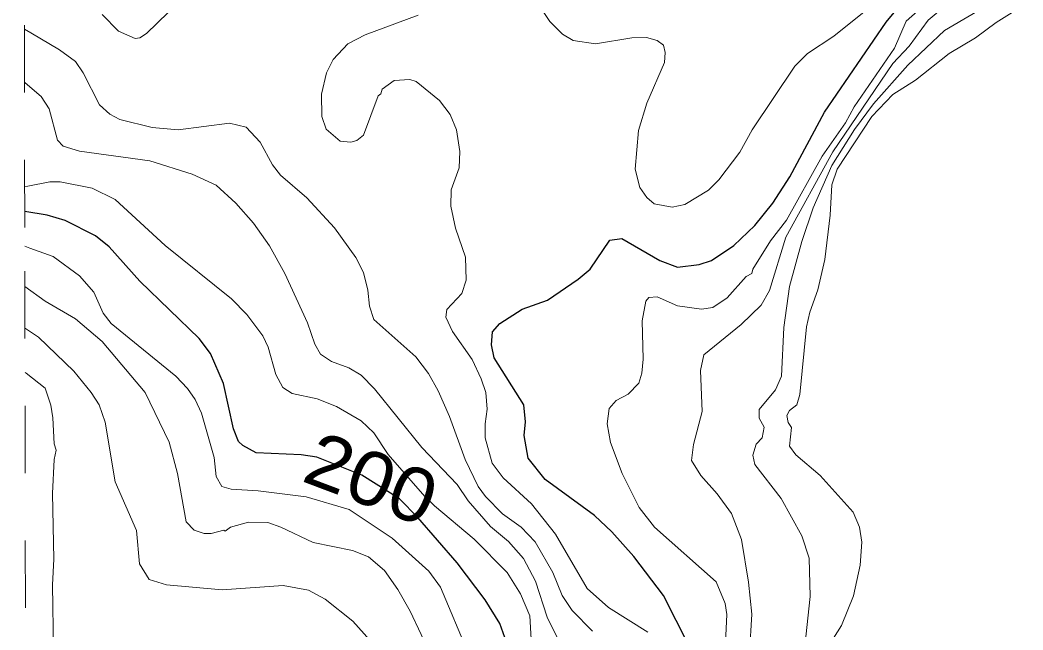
# Model space of a CAD drawing. Extents: x 474.5 to 500, y 7345.7 to 7373.4.
# Drawn here: x 474.546 to 476.034, y 7355.286 to 7356.191 of the extents above; entities that cross this region are included whole.
import ezdxf
from ezdxf.enums import TextEntityAlignment as Align

# ---------------------------------------------------------------- set-up
doc = ezdxf.new("R2010")
doc.units = 0
doc.header["$LTSCALE"] = 0.032
doc.linetypes.add('SHORT_DASHED', pattern=[2.7, 1.5, -1.2])
for name, color, linetype, lineweight in [('1', 7, 'Continuous', 25), ('2', 7, 'Continuous', 13), ('22', 7, 'SHORT_DASHED', 13)]:
    doc.layers.add(name, color=color, linetype=linetype, lineweight=lineweight)
doc.layers.add('61', color=7, linetype='Continuous')

msp = doc.modelspace()

# ---------------------------------------------------------------- linework, layer by layer
at = {"layer": '1'}
for points in [[(475.5384, 7355.2627), (475.5012, 7355.3372), (475.4569, 7355.3951), (475.4242, 7355.4317), (475.3987, 7355.4556), (475.3253, 7355.5092), (475.3002, 7355.5406), (475.2945, 7355.5744), (475.296, 7355.5946), (475.2937, 7355.6201), (475.2499, 7355.6898), (475.2458, 7355.7088), (475.2475, 7355.7283), (475.2583, 7355.7408), (475.2911, 7355.7621), (475.329, 7355.7755), (475.3744, 7355.8064), (475.3923, 7355.8214), (475.4213, 7355.8646), (475.4391, 7355.8669), (475.4957, 7355.834), (475.5219, 7355.8241), (475.554, 7355.8281), (475.5721, 7355.8342), (475.6052, 7355.8566), (475.6365, 7355.886), (475.6634, 7355.9191), (475.6887, 7355.9583), (475.7399, 7356.0545), (475.8315, 7356.1881), (475.8634, 7356.2264)], [(475.2705, 7355.2608), (475.258, 7355.2953), (475.2364, 7355.3308), (475.1947, 7355.3856), (475.1362, 7355.4526), (475.1091, 7355.4803), (475.0534, 7355.5158), (474.9864, 7355.5421), (474.9631, 7355.5457), (474.8964, 7355.5489), (474.8768, 7355.5595), (474.8701, 7355.5656), (474.8629, 7355.5844), (474.8478, 7355.6514), (474.8287, 7355.6961), (474.812, 7355.7185), (474.7238, 7355.8035), (474.6783, 7355.8545), (474.6581, 7355.8709), (474.6131, 7355.8937), (474.5861, 7355.9016), (474.5531, 7355.9068)]]:
    msp.add_lwpolyline(points, dxfattribs=at)
at = {"layer": '2'}
for points in [[(475.9113, 7356.2342), (475.861, 7356.1896), (475.844, 7356.1493), (475.7838, 7356.0622), (475.771, 7356.0383), (475.7367, 7355.9891), (475.6836, 7355.894), (475.6596, 7355.8632), (475.6334, 7355.8214), (475.6321, 7355.8149), (475.6238, 7355.8103), (475.5954, 7355.7787), (475.5741, 7355.7643), (475.5576, 7355.7619), (475.5217, 7355.7671), (475.4915, 7355.7801), (475.4794, 7355.7795), (475.475, 7355.7737), (475.4692, 7355.7448), (475.4708, 7355.6879), (475.469, 7355.6672), (475.4644, 7355.652), (475.4484, 7355.6358), (475.4308, 7355.6264), (475.4204, 7355.6147), (475.4174, 7355.5918), (475.4226, 7355.564), (475.4395, 7355.518), (475.4647, 7355.4677), (475.4879, 7355.4384), (475.5792, 7355.3573), (475.5927, 7355.3252), (475.5952, 7355.309), (475.593, 7355.2671)], [(475.6327, 7356.0282), (475.6143, 7355.9948), (475.583, 7355.9538), (475.5676, 7355.9385), (475.5327, 7355.9173), (475.5139, 7355.9136), (475.4872, 7355.9184), (475.4765, 7355.9275), (475.4659, 7355.9425), (475.4588, 7355.9699), (475.4641, 7356.0273), (475.4762, 7356.0679), (475.5026, 7356.128), (475.5034, 7356.1431), (475.5008, 7356.1536), (475.4914, 7356.1608), (475.4758, 7356.1654), (475.4542, 7356.1646), (475.4003, 7356.156), (475.367, 7356.1606), (475.3512, 7356.1699), (475.3323, 7356.1889), (475.3186, 7356.2096)], [(475.9813, 7356.2125), (475.9183, 7356.1758), (475.8637, 7356.124), (475.8126, 7356.0668), (475.7843, 7356.0285), (475.751, 7355.9754), (475.723, 7355.9122), (475.7062, 7355.8626), (475.6878, 7355.7956), (475.6798, 7355.735), (475.6764, 7355.6624), (475.6675, 7355.642), (475.6431, 7355.6132), (475.6431, 7355.6001), (475.6502, 7355.5868), (475.6476, 7355.5711), (475.6388, 7355.5618), (475.6336, 7355.5451), (475.6368, 7355.5315), (475.6759, 7355.4808), (475.7062, 7355.4257), (475.7171, 7355.3922), (475.7188, 7355.3353), (475.7125, 7355.2758)], [(475.6586, 7355.7899), (475.6826, 7355.8689), (475.7526, 7355.9953), (475.8414, 7356.1265), (475.8655, 7356.1525), (475.894, 7356.1907), (475.9207, 7356.2133)], [(475.7413, 7355.2547), (475.765, 7355.2925), (475.7831, 7355.3364), (475.793, 7355.3819), (475.7954, 7355.4159), (475.792, 7355.4385), (475.7825, 7355.4605), (475.7337, 7355.5149), (475.6972, 7355.5459), (475.6881, 7355.5587), (475.6911, 7355.5864), (475.6863, 7355.5938), (475.6839, 7355.6042), (475.6878, 7355.6118), (475.699, 7355.62), (475.7036, 7355.6351), (475.7134, 7355.7357), (475.7181, 7355.7573), (475.7301, 7355.7908), (475.7405, 7355.8355), (475.7483, 7355.9016), (475.7507, 7355.9466), (475.759, 7355.9698), (475.8102, 7356.0479), (475.8412, 7356.0805), (475.8749, 7356.102), (475.9252, 7356.1414), (475.964, 7356.1648), (475.9946, 7356.1877), (476.0345, 7356.2124)], [(474.6682, 7356.1992), (474.6922, 7356.1746), (474.7168, 7356.1639), (474.7238, 7356.1646), (474.7339, 7356.1709), (474.7659, 7356.2024)], [(475.1371, 7356.1981), (475.0585, 7356.1692), (475.0326, 7356.1556), (475.0108, 7356.1324), (475.0007, 7356.1126), (474.9937, 7356.081), (474.9942, 7356.0481), (475.0003, 7356.0289), (475.0211, 7356.0115), (475.037, 7356.01), (475.0457, 7356.0125), (475.0559, 7356.0204), (475.0774, 7356.0785), (475.0813, 7356.0818), (475.0834, 7356.0883), (475.1015, 7356.1016), (475.1248, 7356.1031), (475.1341, 7356.1), (475.1688, 7356.0718), (475.1842, 7356.0509), (475.194, 7356.028), (475.1987, 7355.9958), (475.1978, 7355.9719), (475.186, 7355.9393), (475.1853, 7355.9149), (475.1925, 7355.8824), (475.2074, 7355.839), (475.2083, 7355.8048), (475.2019, 7355.7852), (475.1794, 7355.7617), (475.178, 7355.7502), (475.188, 7355.7289), (475.2169, 7355.6871), (475.2305, 7355.6584), (475.2372, 7355.6384), (475.2395, 7355.6134), (475.2363, 7355.5917), (475.2363, 7355.571), (475.2467, 7355.5334), (475.2629, 7355.5118), (475.305, 7355.4728), (475.3409, 7355.4281), (475.3879, 7355.3476), (475.4195, 7355.3192), (475.4777, 7355.2825)], [(475.8012, 7356.2055), (475.7536, 7356.1674), (475.7146, 7356.1413), (475.6959, 7356.1226), (475.6327, 7356.0282)], [(475.3955, 7355.2841), (475.3656, 7355.3148), (475.3505, 7355.3372), (475.3366, 7355.3712), (475.3105, 7355.4165), (475.2899, 7355.4384), (475.262, 7355.4583), (475.2371, 7355.484), (475.2258, 7355.499), (475.2066, 7355.5387), (475.1833, 7355.6028), (475.1667, 7355.6408), (475.1523, 7355.6664), (475.1335, 7355.6914), (475.0711, 7355.7467), (475.0648, 7355.7664), (475.0624, 7355.7903), (475.0557, 7355.8166), (475.0446, 7355.8386), (475.013, 7355.8828), (474.9718, 7355.9273), (474.9325, 7355.961), (474.9208, 7355.9762), (474.9024, 7356.0097), (474.8819, 7356.0322), (474.8569, 7356.0378), (474.7809, 7356.0283), (474.7421, 7356.0316), (474.694, 7356.0433), (474.6794, 7356.0513), (474.6642, 7356.0651), (474.6397, 7356.1126), (474.6284, 7356.1295), (474.6047, 7356.147), (474.5622, 7356.1719), (474.5526, 7356.1775)], [(474.5527, 7356.0988), (474.5535, 7356.0981), (474.5775, 7356.0774), (474.5892, 7356.0593), (474.6018, 7356.013), (474.6103, 7356.0039), (474.6342, 7355.9964), (474.7387, 7355.982), (474.8013, 7355.9624), (474.8373, 7355.9461), (474.8665, 7355.9193), (474.8926, 7355.8894), (474.9163, 7355.8559), (474.9393, 7355.8147), (474.9725, 7355.7418), (474.9837, 7355.7099), (474.992, 7355.6951), (475.0081, 7355.6844), (475.0339, 7355.6747), (475.0525, 7355.6638), (475.072, 7355.6435), (475.1422, 7355.5566), (475.1946, 7355.5019), (475.2111, 7355.4775), (475.2444, 7355.4393), (475.2711, 7355.4173), (475.2932, 7355.3919), (475.3111, 7355.3584), (475.3284, 7355.305), (475.3533, 7355.2547)], [(475.3081, 7355.2108), (475.3025, 7355.3069), (475.2887, 7355.3393), (475.2689, 7355.3709), (475.2199, 7355.4207), (475.161, 7355.47), (475.1469, 7355.4841), (475.0922, 7355.5462), (475.071, 7355.5784), (475.0525, 7355.596), (475.0155, 7355.6177), (474.9871, 7355.6287), (474.9501, 7355.6367), (474.9359, 7355.6456), (474.9257, 7355.6648), (474.9141, 7355.7054), (474.9066, 7355.7222), (474.8827, 7355.754), (474.8601, 7355.7773), (474.7615, 7355.8567), (474.6871, 7355.9247), (474.6533, 7355.9415), (474.6058, 7355.9509), (474.5903, 7355.9509), (474.5574, 7355.9446), (474.553, 7355.9438)], [(474.5531, 7355.8555), (474.5607, 7355.8527), (474.5951, 7355.8399), (474.6344, 7355.8116), (474.6556, 7355.7871), (474.6696, 7355.7559), (474.6814, 7355.7406), (474.7773, 7355.6623), (474.7946, 7355.6441), (474.8061, 7355.6281), (474.8154, 7355.6077), (474.8341, 7355.5416), (474.8372, 7355.5135), (474.8457, 7355.4989), (474.8596, 7355.4946), (474.8993, 7355.4922), (474.9708, 7355.4835), (475.0343, 7355.4646), (475.0986, 7355.4223), (475.1528, 7355.373), (475.1699, 7355.3495), (475.2123, 7355.2494)], [(475.1738, 7355.21), (475.1252, 7355.3137), (475.1068, 7355.3457), (475.0869, 7355.3743), (475.0631, 7355.3944), (475.0397, 7355.4037), (474.9812, 7355.4156), (474.9333, 7355.4386), (474.9137, 7355.4452), (474.8852, 7355.4459), (474.8582, 7355.4383), (474.8504, 7355.4326), (474.8484, 7355.4338), (474.8299, 7355.4292), (474.8194, 7355.4292), (474.8045, 7355.4342), (474.7927, 7355.4462), (474.7799, 7355.518), (474.7675, 7355.5646), (474.7319, 7355.6381), (474.668, 7355.7141), (474.6283, 7355.7474), (474.5834, 7355.7739), (474.5533, 7355.7955)], [(475.6287, 7355.2517), (475.6319, 7355.3093), (475.6271, 7355.3568), (475.6167, 7355.4203), (475.6022, 7355.4589), (475.5807, 7355.4877), (475.5563, 7355.5152), (475.5426, 7355.5372), (475.5454, 7355.561), (475.5585, 7355.61), (475.5561, 7355.6709), (475.5608, 7355.6944), (475.6164, 7355.739), (475.6458, 7355.768), (475.6586, 7355.7899)], [(475.0652, 7355.2708), (475.0399, 7355.2991), (474.9988, 7355.3317), (474.9743, 7355.3447), (474.9368, 7355.3517), (474.8461, 7355.3454), (474.7634, 7355.3526), (474.7375, 7355.3608), (474.7232, 7355.384), (474.7191, 7355.4334), (474.6871, 7355.5057), (474.6722, 7355.5943), (474.6634, 7355.6198), (474.6517, 7355.6385), (474.6261, 7355.6698), (474.5734, 7355.7202), (474.5542, 7355.7332), (474.5534, 7355.7338)], [(474.5957, 7355.2558), (474.5941, 7355.3526), (474.5964, 7355.3911), (474.5941, 7355.4883), (474.5968, 7355.539), (474.5995, 7355.5525), (474.5965, 7355.5619), (474.5948, 7355.6009), (474.5917, 7355.6196), (474.5834, 7355.6446), (474.555, 7355.667), (474.5535, 7355.6682)]]:
    msp.add_lwpolyline(points, dxfattribs=at)
at = {"layer": '22'}
msp.add_lwpolyline([(474.5591, 7352.4942), (474.5581, 7353.059), (474.5571, 7353.6239), (474.5561, 7354.1888), (474.5551, 7354.7537), (474.5541, 7355.3185), (474.5531, 7355.8834), (474.5521, 7356.4483), (474.5511, 7357.0132), (474.5501, 7357.578), (474.5491, 7358.1429), (474.5481, 7358.7078), (474.5471, 7359.2727), (474.5461, 7359.8375)], dxfattribs=at)

# ---------------------------------------------------------------- texts
at = {"layer": '61', "width": 1.1}
msp.add_text('200', height=0.08, rotation=339.334, dxfattribs=at).set_placement((475.0534, 7355.473), align=Align.CENTER)

doc.saveas('drawing.dxf')
